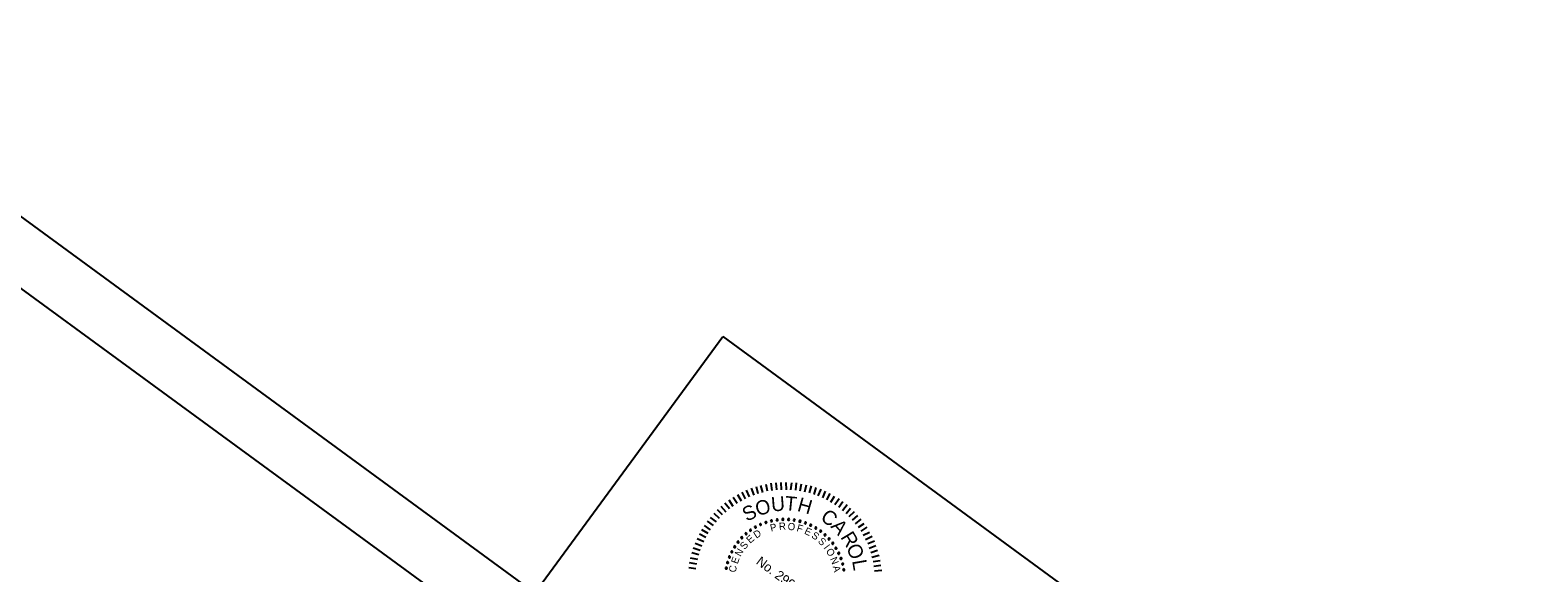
# Model space of a CAD drawing. Extents: x 1970654 to 1970899, y 796145 to 796378.
# Drawn here: x 1970788 to 1970840.2, y 796179.1 to 796197.9 of the extents above; entities that cross this region are included whole.
import ezdxf

# ---------------------------------------------------------------- set-up
doc = ezdxf.new("R2010")
doc.units = 0
for name, color, linetype in [('BR_BORDER LINES', 7, 'Continuous'), ('BR_TEXT', 7, 'Continuous'), ('Level 31', 7, 'Continuous')]:
    doc.layers.add(name, color=color, linetype=linetype)

msp = doc.modelspace()

# ---------------------------------------------------------------- linework, layer by layer
at = {"layer": 'BR_BORDER LINES'}
for p, q in [((1970738.359, 796227.562), (1970847.014, 796148.01)), ((1970805.492, 796178.411), (1970811.99, 796187.287)), ((1970811.99, 796187.287), (1970829.306, 796174.609))]:
    msp.add_line(p, q, dxfattribs=at)
at = {"layer": 'BR_TEXT'}
for p, q in [((1970813.383, 796181.89), (1970813.316, 796182.133)), ((1970813.539, 796181.933), (1970813.499, 796182.172)), ((1970813.706, 796181.962), (1970813.668, 796182.209)), ((1970813.866, 796181.981), (1970813.837, 796182.224)), ((1970814.03, 796181.983), (1970814.019, 796182.239)), ((1970814.199, 796181.985), (1970814.193, 796182.242)), ((1970814.349, 796181.98), (1970814.379, 796182.227)), ((1970814.519, 796181.973), (1970814.549, 796182.22)), ((1970814.672, 796181.949), (1970814.72, 796182.191)), ((1970814.832, 796181.916), (1970814.888, 796182.152)), ((1970814.997, 796181.879), (1970815.067, 796182.117)), ((1970812.354, 796181.411), (1970812.209, 796181.63)), ((1970812.489, 796181.512), (1970812.353, 796181.72)), ((1970812.637, 796181.595), (1970812.512, 796181.812)), ((1970812.78, 796181.672), (1970812.664, 796181.896)), ((1970812.917, 796181.741), (1970812.819, 796181.972)), ((1970813.082, 796181.802), (1970812.987, 796182.036)), ((1970813.221, 796181.845), (1970813.155, 796182.09)), ((1970815.154, 796181.826), (1970815.22, 796182.063)), ((1970815.294, 796181.772), (1970815.396, 796182.001)), ((1970815.451, 796181.707), (1970815.546, 796181.932)), ((1970815.596, 796181.638), (1970815.711, 796181.855)), ((1970815.733, 796181.557), (1970815.865, 796181.763)), ((1970815.866, 796181.471), (1970816.02, 796181.677)), ((1970816.007, 796181.379), (1970816.154, 796181.577)), ((1970811.876, 796180.993), (1970811.694, 796181.163)), ((1970811.988, 796181.115), (1970811.811, 796181.285)), ((1970812.107, 796181.206), (1970811.943, 796181.405)), ((1970812.23, 796181.324), (1970812.069, 796181.517)), ((1970816.136, 796181.27), (1970816.295, 796181.472)), ((1970816.259, 796181.165), (1970816.418, 796181.35)), ((1970816.372, 796181.059), (1970816.551, 796181.23)), ((1970816.483, 796180.938), (1970816.669, 796181.095)), ((1970811.488, 796180.473), (1970811.272, 796180.596)), ((1970811.572, 796180.603), (1970811.362, 796180.751)), ((1970811.669, 796180.745), (1970811.468, 796180.894)), ((1970811.773, 796180.873), (1970811.567, 796181.026)), ((1970816.591, 796180.807), (1970816.786, 796180.965)), ((1970816.685, 796180.686), (1970816.891, 796180.819)), ((1970816.78, 796180.55), (1970816.989, 796180.686)), ((1970811.264, 796180.028), (1970811.033, 796180.127)), ((1970811.342, 796180.179), (1970811.109, 796180.285)), ((1970811.404, 796180.33), (1970811.186, 796180.446)), ((1970816.855, 796180.409), (1970817.076, 796180.522)), ((1970816.93, 796180.267), (1970817.162, 796180.373)), ((1970817.008, 796180.119), (1970817.239, 796180.217)), ((1970817.058, 796179.962), (1970817.294, 796180.056)), ((1970811.127, 796179.569), (1970810.877, 796179.618)), ((1970811.16, 796179.728), (1970810.922, 796179.799)), ((1970811.214, 796179.881), (1970810.965, 796179.96)), ((1970817.114, 796179.814), (1970817.35, 796179.89)), ((1970817.157, 796179.653), (1970817.405, 796179.716)), ((1970817.199, 796179.497), (1970817.443, 796179.538)), ((1970811.063, 796179.253), (1970810.814, 796179.28)), ((1970811.096, 796179.412), (1970810.843, 796179.451)), ((1970817.224, 796179.342), (1970817.467, 796179.379)), ((1970817.242, 796179.175), (1970817.493, 796179.197))]:
    msp.add_line(p, q, dxfattribs=at)
for centre, start, end in [((1970812.954, 796180.584), 35.3174, 215.3174), ((1970812.954, 796180.584), 215.3174, 35.3174), ((1970813.122, 796180.69), 29.779, 209.779), ((1970813.122, 796180.69), 209.779, 29.779), ((1970813.3, 796180.781), 24.2405, 204.2405), ((1970813.3, 796180.781), 204.2405, 24.2405), ((1970813.486, 796180.853), 18.702, 198.702), ((1970813.486, 796180.853), 198.702, 18.702), ((1970813.677, 796180.908), 13.1636, 193.1636), ((1970813.677, 796180.908), 193.1636, 13.1636), ((1970813.874, 796180.943), 7.6251, 187.6251), ((1970813.874, 796180.943), 187.6251, 7.6251), ((1970814.072, 796180.96), 2.0866, 182.0866), ((1970814.072, 796180.96), 182.0866, 2.0866), ((1970814.271, 796180.957), 356.5482, 176.5482), ((1970814.271, 796180.957), 176.5482, 356.5482), ((1970814.47, 796180.935), 351.0097, 171.0097), ((1970814.47, 796180.935), 171.0097, 351.0097), ((1970814.665, 796180.894), 345.4713, 165.4713), ((1970814.665, 796180.894), 165.4713, 345.4713), ((1970814.855, 796180.834), 159.9328, 339.9328), ((1970814.855, 796180.834), 339.9328, 159.9328), ((1970815.038, 796180.757), 154.3943, 334.3943), ((1970815.038, 796180.757), 334.3943, 154.3943), ((1970815.214, 796180.661), 148.8559, 328.8559), ((1970815.214, 796180.661), 328.8559, 148.8559), ((1970815.379, 796180.55), 143.3174, 323.3174), ((1970815.379, 796180.55), 323.3174, 143.3174), ((1970812.406, 796180.011), 57.4713, 237.4713), ((1970812.406, 796180.011), 237.4713, 57.4713), ((1970812.522, 796180.173), 51.9328, 231.9328), ((1970812.522, 796180.173), 231.9328, 51.9328), ((1970812.652, 796180.324), 46.3943, 226.3943), ((1970812.652, 796180.324), 226.3943, 46.3943), ((1970812.797, 796180.461), 40.8559, 220.8559), ((1970812.797, 796180.461), 220.8559, 40.8559), ((1970815.532, 796180.423), 137.779, 317.779), ((1970815.532, 796180.423), 317.779, 137.779), ((1970815.673, 796180.282), 132.2405, 312.2405), ((1970815.673, 796180.282), 312.2405, 132.2405), ((1970815.799, 796180.128), 126.702, 306.702), ((1970815.799, 796180.128), 306.702, 126.702), ((1970812.161, 796179.468), 74.0866, 254.0866), ((1970812.161, 796179.468), 254.0866, 74.0866), ((1970812.225, 796179.656), 68.5482, 248.5482), ((1970812.225, 796179.656), 248.5482, 68.5482), ((1970812.307, 796179.838), 63.0097, 243.0097), ((1970812.307, 796179.838), 243.0097, 63.0097), ((1970815.91, 796179.962), 121.1636, 301.1636), ((1970815.91, 796179.962), 301.1636, 121.1636), ((1970816.005, 796179.786), 115.6251, 295.6251), ((1970816.005, 796179.786), 295.6251, 115.6251), ((1970816.082, 796179.603), 110.0866, 290.0866), ((1970816.082, 796179.603), 290.0866, 110.0866), ((1970812.115, 796179.274), 79.6251, 259.6251), ((1970812.115, 796179.274), 259.6251, 79.6251), ((1970816.141, 796179.412), 104.5482, 284.5482), ((1970816.141, 796179.412), 284.5482, 104.5482), ((1970816.181, 796179.217), 99.0097, 279.0097), ((1970816.181, 796179.217), 279.0097, 99.0097)]:
    msp.add_arc(centre, 0.028, start, end, dxfattribs=at)
at = {"layer": 'Level 31'}
msp.add_lwpolyline([(1970731.261, 796230.28), (1970847.449, 796145.214), (1970899.434, 796216.218), (1970783.245, 796301.284)], close=True, dxfattribs=at)

# ---------------------------------------------------------------- texts
at = {"layer": 'BR_TEXT'}
for s, height, rotation, p in [('O', 0.496, 15.8173, (1970813.199, 796181.07)), ('U', 0.496, 4.5928, (1970813.685, 796181.23)), ('T', 0.496, 354.2898, (1970814.124, 796181.279)), ('H', 0.496, 344.1543, (1970814.543, 796181.257)), ('S', 0.496, 27.0417, (1970812.827, 796180.869)), ('C', 0.496, 323.3388, (1970815.341, 796180.962)), ('D', 0.249, 32.827, (1970813.154, 796180.288)), ('P', 0.249, 13.7327, (1970813.666, 796180.534)), ('R', 0.249, 4.1855, (1970813.945, 796180.59)), ('O', 0.249, 354.6383, (1970814.23, 796180.599)), ('F', 0.249, 344.4033, (1970814.533, 796180.556)), ('E', 0.249, 335.2009, (1970814.794, 796180.472)), ('A', 0.496, 311.9887, (1970815.703, 796180.701)), ('R', 0.496, 301.225, (1970816.053, 796180.346)), ('S', 0.249, 51.5766, (1970812.756, 796179.896)), ('E', 0.249, 42.0294, (1970812.943, 796180.112)), ('S', 0.249, 325.9986, (1970815.039, 796180.348)), ('S', 0.249, 316.4514, (1970815.269, 796180.179)), ('I', 0.249, 306.9042, (1970815.467, 796179.974)), ('O', 0.496, 290.3775, (1970816.264, 796180.009)), ('E', 0.249, 70.3261, (1970812.506, 796179.398)), ('N', 0.249, 61.1237, (1970812.609, 796179.653)), ('No. 29964', 0.327, 323.3174, (1970813.121, 796179.439)), ('O', 0.249, 302.2298, (1970815.551, 796179.862)), ('N', 0.249, 291.9947, (1970815.701, 796179.596)), ('L', 0.496, 279.7394, (1970816.467, 796179.525)), ('C', 0.249, 80.2172, (1970812.443, 796179.109)), ('A', 0.249, 282.4476, (1970815.797, 796179.328))]:
    msp.add_text(s, height=height, rotation=rotation, dxfattribs=at).set_placement(p)

doc.saveas('drawing.dxf')
